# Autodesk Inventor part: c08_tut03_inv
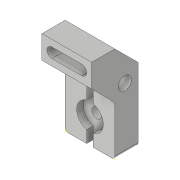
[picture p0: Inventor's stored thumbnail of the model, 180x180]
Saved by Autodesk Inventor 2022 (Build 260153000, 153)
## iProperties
Created: 2015-03
Part Number: c08_tut03_inv
Material: Generic
Document SubType Name: Modeling
Designer: Sandeep
Density: 1 g/cm^3
Appearance: Default
Author: Sandeep
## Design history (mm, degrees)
sketch "Sketch1"
  geometry: L1 (0, 0)-(0, 30); L2 (0, 30)-(-14, 44); L3 (-14, 44)-(-14, 58); L4 (-14, 58)-(0, 58); L5 (14, 44)-(14, 0); L6 (14, 0)-(0, 0); L7 (0, 58)-(14, 44)
  constraints: 14 end point, 3 parallel, 1 horizontal, 1 perpendicular, 1 vertical
  dimensions: "d0" = 14 distance between parallel lines of L5 L1; "d1" = 14 distance from line of L4.end L5; "d2" = 14 horizontal distance of L4.end L5.start; "d3" = 28 distance between parallel lines of L3 L5; "d4" = 58 distance between parallel lines of L4 L6; "d5" = 14 distance of L2.end L3.end
extrude "Extrusion1" new body sketch "Sketch1" distance "d6" = 30; taper "d7" = 0 deg
sketch "Sketch2"
  geometry: 1 further point
hole "Hole1" diameter "d10" = 8; stored, may be unused: countersink angle "d14" = 90 deg, drill point angle "d16" = 118 deg; dims "d8" = 21, "d9" = 8, "d11" = 6, "d12" = 4, "d13" = 2, "d15" = 8
sketch "Sketch3"
  geometry: L1 (0, 0)-(30, 0) reference; L2 (0, -30)-(30, -30) reference; L3 (30, 0)-(30, -30) reference; L4 (13, 0)-(13, -7.254); L5 (0, 3)-(30, 3) reference; L6 (17, 0)-(17, -7.254); L7 (15, -15)-(15, 7.075); L8 (13, 0)-(17, 0); L9 (-6.754, -15)-(33.848, -15); L10 (13, -22.746)-(13, -30); L11 (17, -30)-(17, -22.746); C1 r 3 at (15, -15); A1 r 8 centre (15, -15) between (13, -7.254) and (13, -22.746); A2 r 8 centre (15, -15) between (17, -22.746) and (17, -7.254)
  constraints: 14 end point, 5 point on line, 4 point on circle, 3 centre point, 2 parallel, 2 perpendicular, 1 coincident, 1 collinear, 1 horizontal, 1 vertical, 2 other
  dimensions: "d19" = 6 diameter of C1; "d21" = 15 distance from line of L2 A1.centre; "d22" = 15 distance from line of A1.centre L3; "d23" = 4 distance between parallel lines of L6 L4; "d24" = 4 distance between parallel lines of L11 L10; "d25" = 8 radius of A2; "d26" = 8 radius of A1
sketch "Sketch4"
  geometry: 1 further point
extrude "Extrusion2" cut sketch "Sketch3" distance "d27" = 4; taper "d28" = 0 deg
sketch "Sketch5"
  geometry: L1 (6, 7)-(24, 7); L2 (6, 4)-(24, 4); L3 (24, 10)-(6, 10); L4 (0, 14)-(30, 14) reference; L5 (30, 0)-(30, 14) reference; A1 r 3 centre (6, 7) between (6, 10) and (6, 4); A2 r 3 centre (24, 7) between (24, 4) and (24, 10); 2 further points
  constraints: 8 end point, 4 point on circle, 4 tangent, 2 centre point, 1 horizontal, 1 midpoint, 1 parallel
  dimensions: "d29" = 7 distance between parallel lines of L4 L1; "d30" = 18 distance of L1.start L1.end; "d31" = 6 distance from line of L5 L1.end; "d32" = 3 radius of A2
extrude "Extrusion3" cut sketch "Sketch5" distance "d33" = 11; taper "d34" = 0 deg
sketch "Sketch6"
  geometry: C1 r 3 at (0, 0); C2 r 3 at (0, 0) reference; 1 further point
  constraints: 1 centre point, 1 concentric
extrude "Extrusion4" cut sketch "Sketch6" distance "d35" = 35.25; taper "d36" = 0 deg
fillet "Fillet2" dims "d37" = 2
body "Solid1"
other parameters: "d20" = 16
